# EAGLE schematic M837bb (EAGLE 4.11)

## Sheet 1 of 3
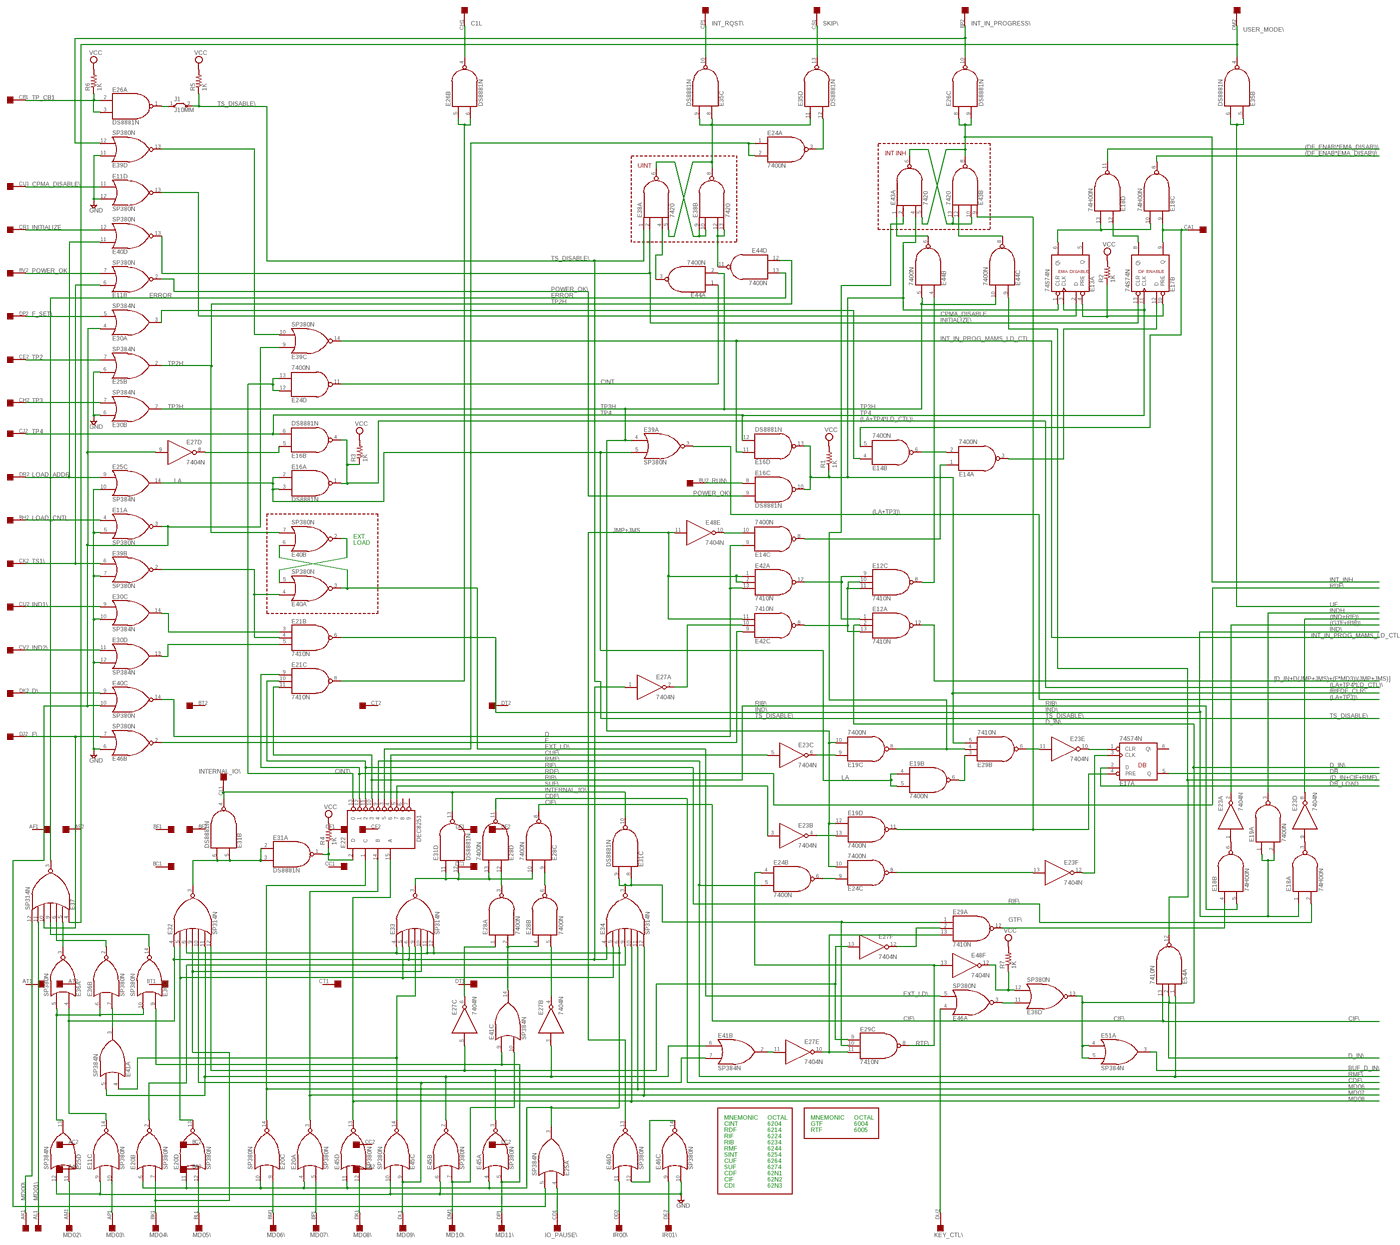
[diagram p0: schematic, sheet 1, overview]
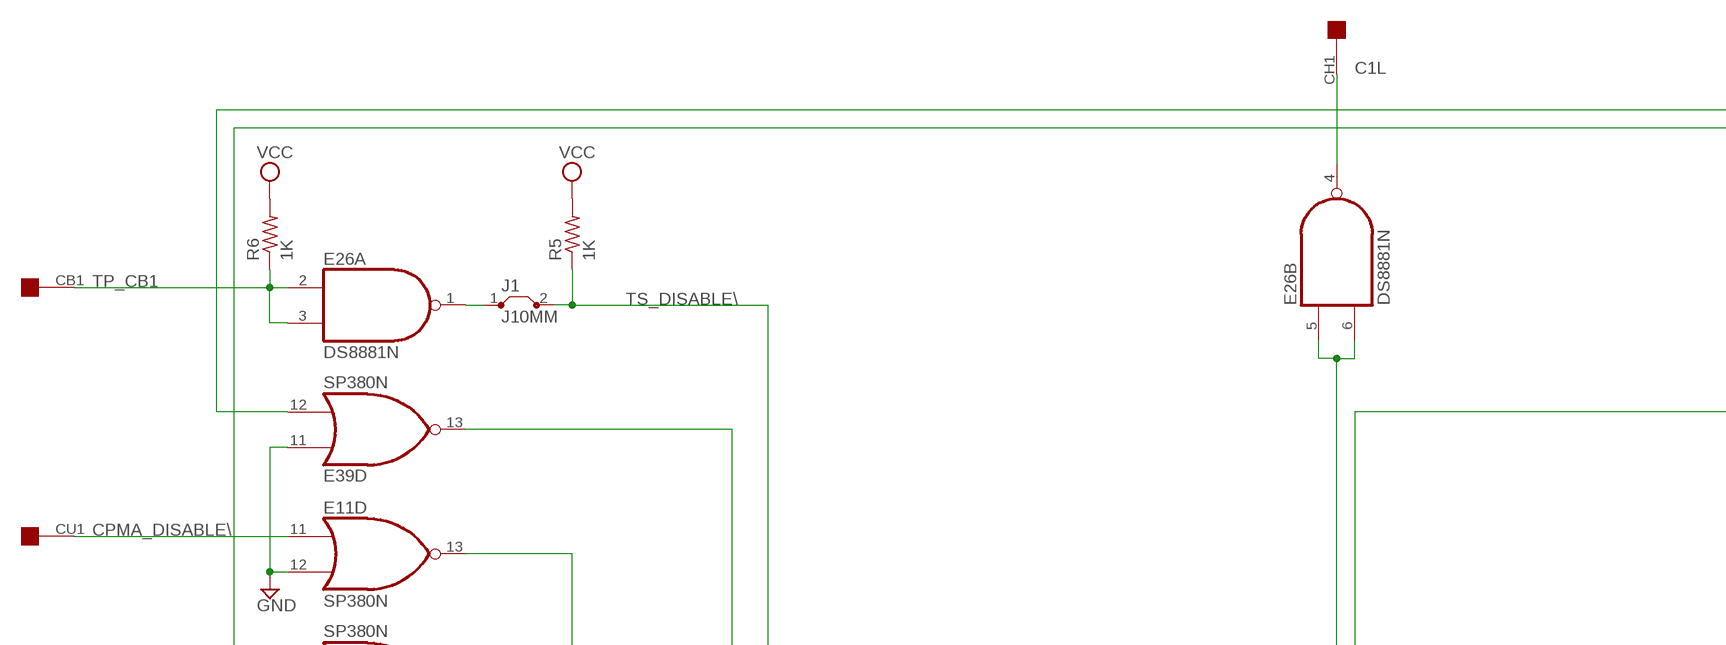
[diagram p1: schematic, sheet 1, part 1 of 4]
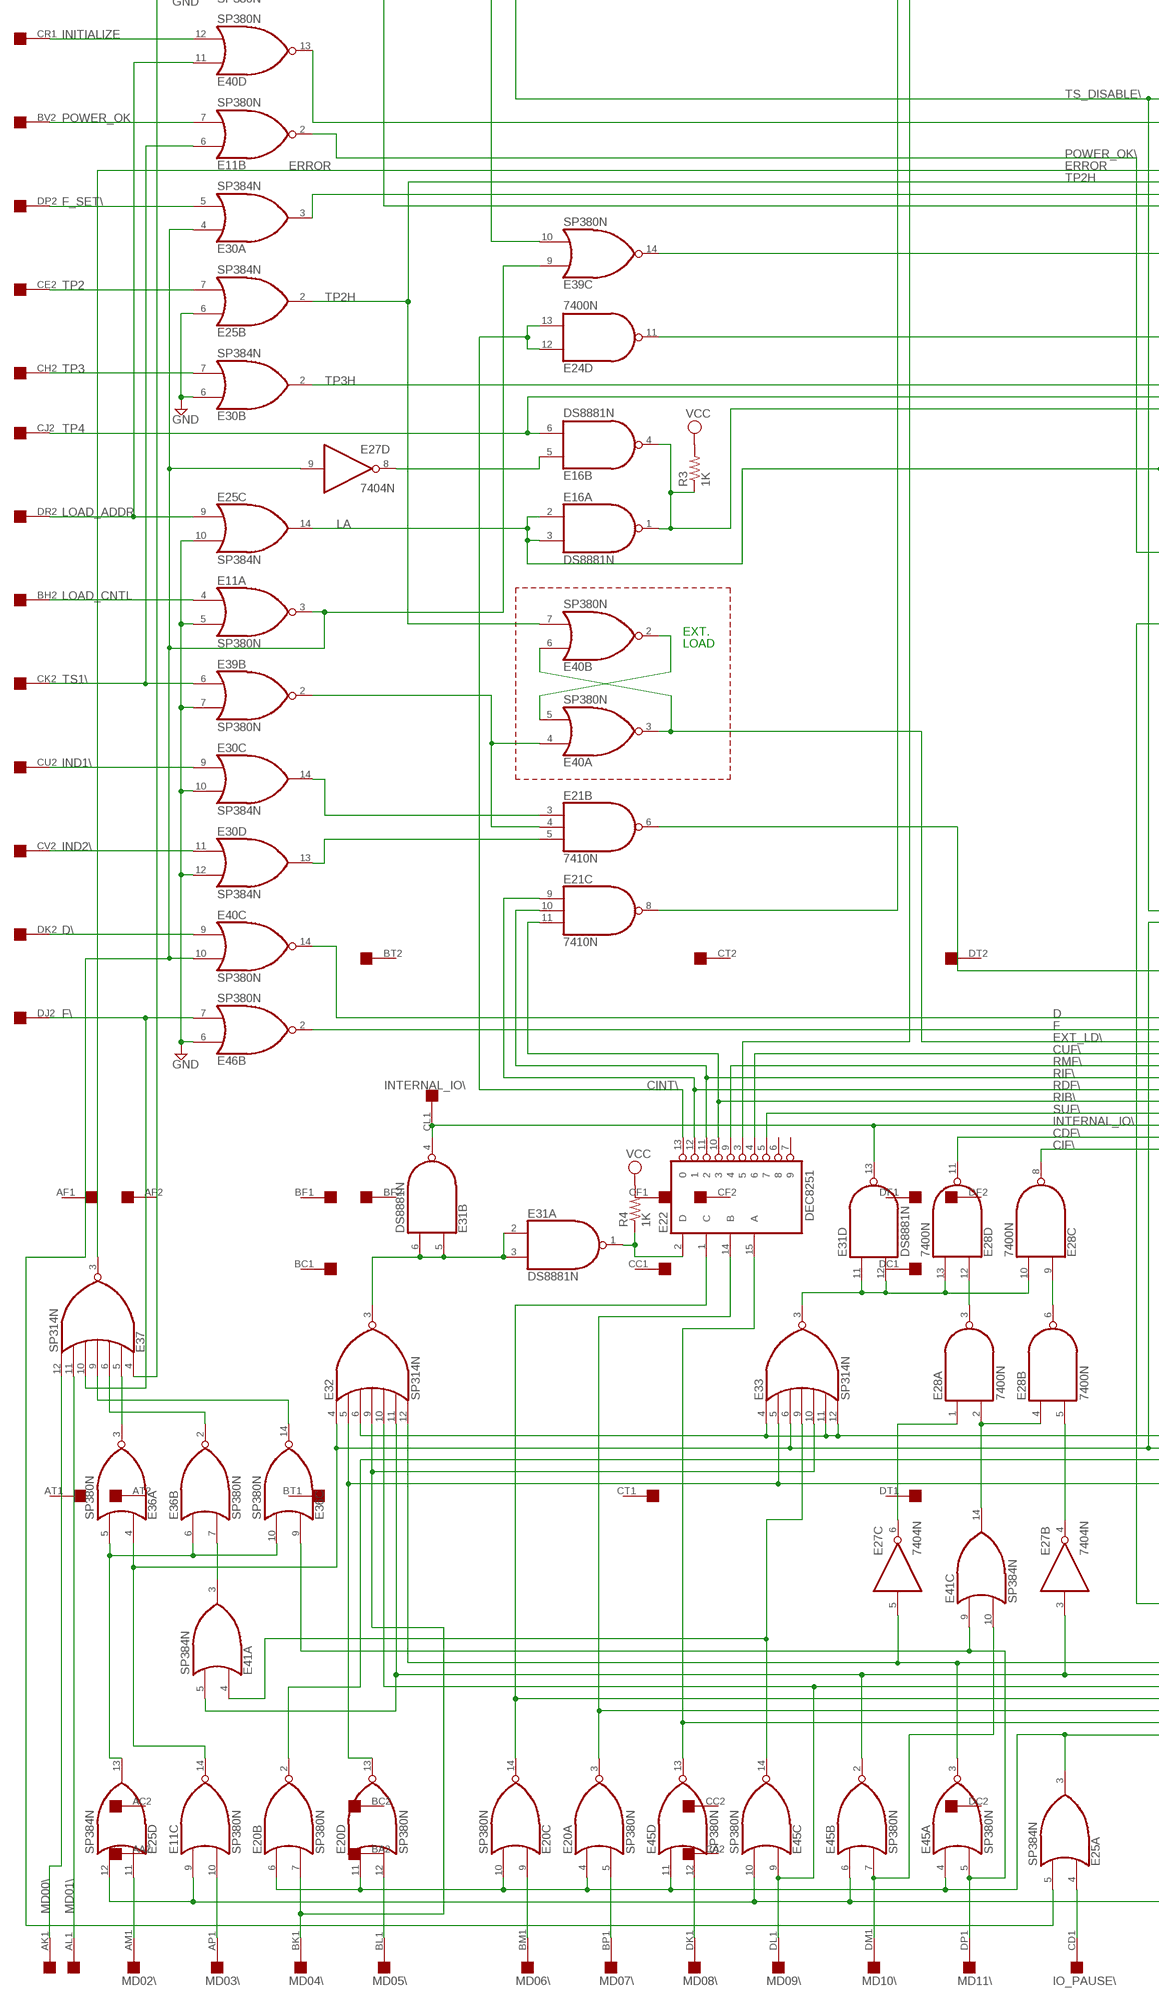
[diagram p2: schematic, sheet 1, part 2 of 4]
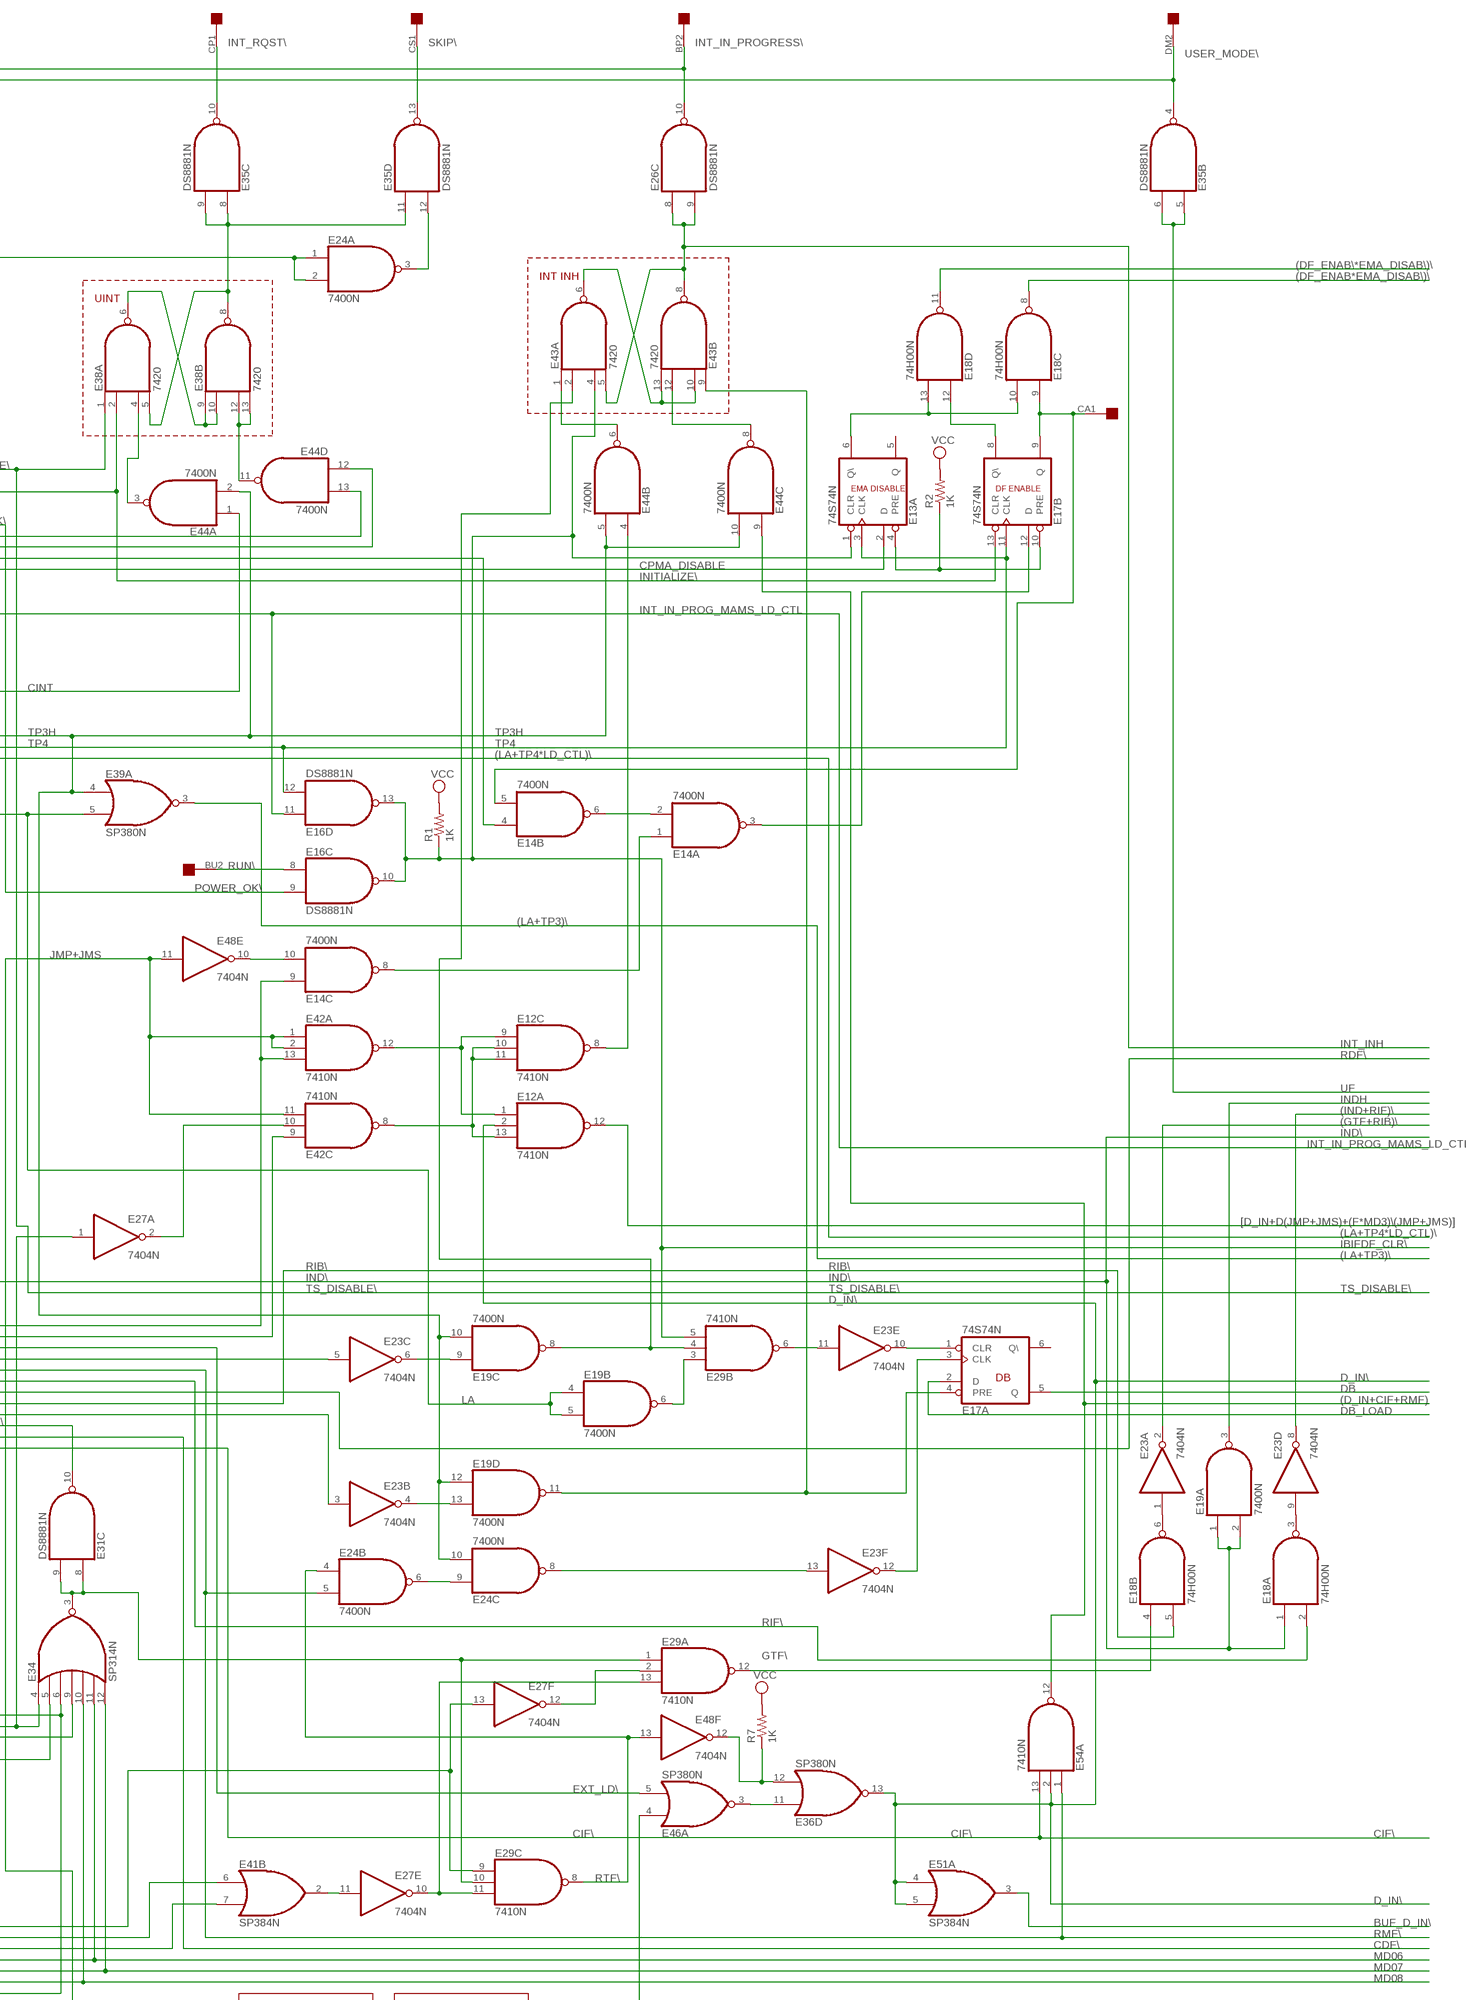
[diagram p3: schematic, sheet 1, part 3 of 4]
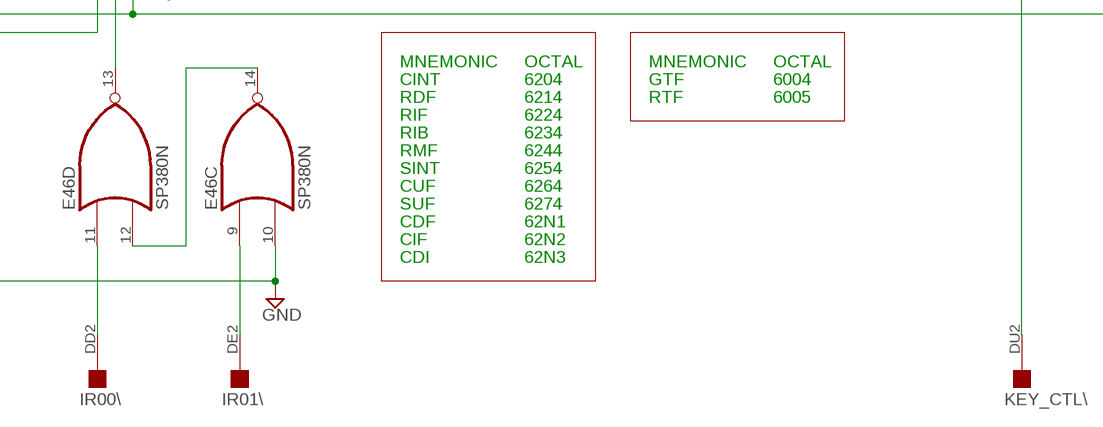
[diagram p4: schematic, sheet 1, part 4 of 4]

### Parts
E11  SP380N  [DIL14]
E12  7410N  [DIL14]
E13  74S74N  [DIL14]
E14  7400N  [DIL14]
E16  DS8881N  [DIL14]
E17  74S74N  [DIL14]
E18  74H00N  74S00N  [DIL14]
E19  7400N  [DIL14]
E20  SP380N  [DIL14]
E21  7410N  [DIL14]
E22  DEC8251  [DIL16]
E23  7404N  [DIL14]
E24  7400N  [DIL14]
E25  SP384N  [DIL14]
E26  DS8881N  [DIL14]
E27  7404N  [DIL14]
E28  7400N  [DIL14]
E29  7410N  74S10N  [DIL14]
E30  SP384N  [DIL14]
E31  DS8881N  [DIL14]
E32  SP314N  [DIL14]
E33  SP314N  [DIL14]
E34  SP314N  [DIL14]
E35  DS8881N  [DIL14]
E36  SP380N  [DIL14]
E37  SP314N  [DIL14]
E38  7420  74S20N  [DIL14]
E39  SP380N  [DIL14]
E40  SP380N  [DIL14]
E41  SP384N  [DIL14]
E42  7410N  [DIL14]
E43  7420  74S20N  [DIL14]
E44  7400N  [DIL14]
E45  SP380N  [DIL14]
E46  SP380N  [DIL14]
E48  7404N  [DIL14]
E51  SP384N  [DIL14]
E54  7410N  [DIL14]
EDGE  QUAD  [EDGE-CON8]
J1  J10MM  [10]
R1  1K  R-US_0207/10  [0207/10]
R2  1K  R-US_0207/10  [0207/10]
R3  1K  R-US_0207/10  [0207/10]
R4  1K  R-US_0207/10  [0207/10]
R5  1K  R-US_0207/10  [0207/10]
R6  1K  R-US_0207/10  [0207/10]
R7  1K  R-US_0207/10  [0207/10]

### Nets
(D_IN+CIF+RMF): E44.9(C:I0) E54.12(A:O) ; also sheet 2
(DF_ENAB*EMA_DISAB\)\: E18.8(C:O) ; also sheet 2
(DF_ENAB\*EMA_DISAB\)\: E18.11(D:O) ; also sheet 2
(GTF+RIB)\: E23.2(A:O) ; also sheet 2
(IND+RIF)\: E23.8(D:O) ; also sheet 2
(LA+TP3)\: E39.3(A:O) ; also sheet 2
(LA+TP4*LD_CTL)\: E16.1(A:O) E16.4(B:O) R3.1 ; also sheet 2
[D_IN+D(JMP+JMS)+(F*MD3)\(JMP+JMS)]: E12.12(A:O) ; also sheet 2
BUF_D_IN\: E51.3(A:O) ; also sheet 2
C1L: E26.4(B:O) EDGE.CH1
CDF\: E28.11(D:O) ; also sheet 2
CIF\: E28.8(C:O) E54.13(A:I2) ; also sheet 2
CINT: E24.11(D:O) E44.1(A:I0)
CINT\: E22.13 E24.12(D:I0) E24.13(D:I1)
CPMA_DISABLE: E11.13(D:O) E13.2(A:D)
CPMA_DISABLE\: E11.11(D:I0) EDGE.CU1
CUF\: E22.4 E23.5(C:I)
D: E14.9(C:I0) E40.14(C:O) E42.13(A:I2)
D\: E40.9(C:I0) EDGE.DK2
D_IN\: E12.2(A:I1) E36.13(D:O) E51.4(A:I0) E51.5(A:I1) E54.2(A:I1) ; also sheet 2
DB: E17.5(A:Q) ; also sheet 2
DB_LOAD: E17.2(A:D) ; also sheet 2
ERROR: E37.3(O) E44.13(D:I1)
EXT_LD\: E40.3(A:O) E40.6(B:I0) E46.5(A:I1)
F: E42.9(C:I0) E46.2(B:O)
F\: E37.10(I4) E46.7(B:I1) EDGE.DJ2
F_SET\: E30.5(A:I1) EDGE.DP2
GND [Supply]: E11.5(A:I1) E11.9(C:I0) E11.12(D:I1) E25.6(B:I0) E25.10(C:I1) E25.12(D:I1) E30.6(B:I0) E30.10(C:I1) E30.12(D:I1) E39.7(B:I1) E39.11(D:I0) E45.6(B:I0) E45.10(C:I1) E46.6(B:I0) E46.10(C:I1) ; also sheet 2,3
GTF\: E18.4(B:I0) E29.12(A:O)
IBIFDF_CLR\: E13.1(A:CLR) E16.10(C:O) E16.13(D:O) E29.5(B:I2) E43.4(A:I2) R1.1 ; also sheet 2
IND1\: E30.9(C:I0) EDGE.CU2
IND2\: E30.11(D:I0) EDGE.CV2
IND\: E18.1(A:I0) E19.1(A:I0) E19.2(A:I1) E21.6(B:O) ; also sheet 2
INDH: E19.3(A:O) ; also sheet 2
INITIALIZE: E40.12(D:I1) EDGE.CR1
INITIALIZE\: E17.13(B:CLR) E38.2(A:I1) E40.13(D:O)
INT_IN_PROG_MAMS_LD_CTL: E16.11(D:I0) E39.14(C:O) ; also sheet 2
INT_IN_PROGRESS\: E26.10(C:O) E39.12(D:I1) EDGE.BP2
INT_INH: E26.8(C:I0) E26.9(C:I1) E43.5(A:I3) E43.8(B:O) ; also sheet 2
INT_RQST\: E35.10(C:O) EDGE.CP1
INTERNAL_IO\: E31.4(B:O) E31.10(C:O) E31.13(D:O) EDGE.CL1
IO_PAUSE\: E25.4(A:I0) EDGE.CD1
IR00\: E46.11(D:I0) EDGE.DD2
IR01\: E46.9(C:I0) EDGE.DE2
JMP+JMS: E42.1(A:I0) E42.2(A:I1) E42.11(C:I2) E46.13(D:O) E48.11(E:I)
KEY_CTL\: E46.4(A:I0) EDGE.DU2
LA: E16.2(A:I0) E16.3(A:I1) E19.4(B:I0) E19.5(B:I1) E25.14(C:O) E39.5(A:I1)
LOAD_ADDR: E25.9(C:I0) E40.11(D:I0) EDGE.DR2
LOAD_CNTL: E11.4(A:I0) EDGE.BH2
MD00\: E37.12(I6) EDGE.AK1
MD01\: E37.11(I5) EDGE.AL1
MD02\: E25.11(D:I0) EDGE.AM1
MD03: E11.14(C:O) E27.1(A:I) E32.4(I0) E33.6(I2) E34.4(I0) E36.4(A:I0)
MD03\: E11.10(C:I1) EDGE.AP1
MD04\: E20.7(B:I1) E32.9(I3) E33.10(I4) EDGE.BK1
MD05\: E20.12(D:I1) EDGE.BL1
MD06: E20.14(C:O) E22.1(C) E34.11(I5) ; also sheet 2
MD06\: E20.9(C:I0) EDGE.BM1
MD07: E20.3(A:O) E22.14(B) E34.12(I6) ; also sheet 2
MD07\: E20.5(A:I1) EDGE.BP1
MD08: E22.15(A) E34.10(I4) E45.13(D:O) ; also sheet 2
MD08\: E45.12(D:I1) EDGE.DK1
MD09\: E32.10(I4) E41.7(B:I1) E45.9(C:I0) EDGE.DL1
MD10\: E41.10(C:I1) E45.7(B:I1) EDGE.DM1
MD11\: E36.9(C:I0) E41.9(C:I0) E45.5(A:I1) EDGE.DP1
N$1: E24.3(A:O) E35.12(D:I1)
N$2 [Supply]: E26.1(A:O) J1.1
N$3: E27.10(E:O) E29.11(C:I2) E29.13(A:I2)
N$4 [Supply]: E22.2(D) E31.1(A:O) R4.1
N$5 [Supply]: E31.2(A:I0) E31.3(A:I1) E31.5(B:I0) E31.6(B:I1) E32.3(O)
N$6: E36.3(A:O) E37.5(I1)
N$7: E11.3(A:O) E25.5(A:I1) E27.9(D:I) E30.4(A:I0) E39.9(C:I0) E40.10(C:I1)
N$8: E36.2(B:O) E37.6(I2)
N$9: E36.14(C:O) E37.9(I3)
N$11: E14.2(A:I1) E14.6(B:O)
N$12: E46.12(D:I1) E46.14(C:O)
N$13: E38.4(A:I2) E44.3(A:O)
N$14: E40.2(B:O) E40.5(A:I1)
N$15: E21.4(B:I1) E39.2(B:O) E40.4(A:I0)
N$16: E21.5(B:I2) E30.13(D:O)
N$17: E21.3(B:I0) E30.14(C:O)
N$18: E35.8(C:I0) E35.9(C:I1) E35.11(D:I0) E38.5(A:I3) E38.8(B:O)
N$19: E27.11(E:I) E41.2(B:O)
N$21: E38.12(B:I2) E38.13(B:I3) E44.11(D:O)
N$22: E20.4(A:I0) E20.6(B:I0) E20.10(C:I1) E20.11(D:I0) E25.3(A:O) E32.6(I2) E33.4(I0) E33.11(I5) E33.12(I6) E34.6(I2) E45.4(A:I0) E45.11(D:I0)
N$23: E38.6(A:O) E38.9(B:I0) E38.10(B:I1)
N$24: E23.13(F:I) E24.8(C:O)
N$25: E43.6(A:O) E43.10(B:I1) E43.13(B:I3)
N$26: E25.13(D:O) E36.5(A:I1) E36.6(B:I0) E36.10(C:I1)
N$27: E29.1(A:I0) E29.10(C:I1) E31.8(C:I0) E31.9(C:I1) E34.3(O)
N$28: E14.1(A:I0) E14.8(C:O)
N$29: E36.7(B:I1) E41.3(A:O)
N$30: E33.9(I3) E41.4(A:I0) E45.14(C:O)
N$31: E27.3(B:I) E32.11(I5) E41.5(A:I1) E41.6(B:I0) E45.2(B:O)
N$32: E17.3(A:CLK) E23.12(F:O)
N$33: E20.2(B:O) E34.9(I3)
N$34: E20.13(D:O) E32.5(I1) E33.5(I1) E34.5(I1)
N$35: E36.12(D:I1) E48.12(F:O) R7.1
N$36: E14.10(C:I1) E48.10(E:O)
N$37: E18.3(A:O) E23.9(D:I)
N$38: E21.8(C:O) E26.5(B:I0) E26.6(B:I1)
N$39: E16.5(B:I0) E27.8(D:O)
N$40: E12.10(C:I1) E12.11(C:I2) E12.13(A:I2) E42.8(C:O)
N$41: E39.10(C:I1) E39.13(D:O)
N$42: E13.4(A:PRE) E17.10(B:PRE) R2.1
N$43: E14.4(B:I0) E30.3(A:O)
N$44: E12.1(A:I0) E12.9(C:I0) E42.12(A:O)
N$47: E18.6(B:O) E23.1(A:I)
N$48: E27.2(A:O) E42.10(C:I1)
N$49: E14.3(A:O) E17.12(B:D)
N$50: E28.2(A:I1) E28.4(B:I0) E41.14(C:O)
N$51: E13.6(A:Q\) E18.10(C:I1) E18.13(D:I1)
N$52: E19.6(B:O) E29.3(B:I0)
N$53: E19.8(C:O) E29.4(B:I1) E43.2(A:I1)
N$54: E28.10(C:I1) E28.13(D:I1) E31.11(D:I0) E31.12(D:I1) E33.3(O)
N$55: E28.3(A:O) E28.12(D:I0)
N$56: E28.6(B:O) E28.9(C:I0)
N$57: E27.5(C:I) E27.13(F:I) E29.9(C:I0) E32.12(I6) E45.3(A:O)
N$58: E27.6(C:O) E28.1(A:I0)
N$59: E27.4(B:O) E28.5(B:I1)
N$61: E17.8(B:Q\) E18.12(D:I0)
N$62: E24.6(B:O) E24.9(C:I0)
N$63: E19.13(D:I1) E23.4(B:O)
N$64: E19.9(C:I0) E23.6(C:O)
N$65: E17.1(A:CLR) E23.10(E:O)
N$66: E23.11(E:I) E29.6(B:O)
N$67: E27.12(F:O) E29.2(A:I1)
N$68: E36.11(D:I0) E46.3(A:O)
N$69: E17.4(A:PRE) E19.11(D:O) E43.9(B:I0)
N$70: E14.5(B:I1) E17.9(B:Q) E18.9(C:I0) EDGE.CA1
N$71: E12.8(C:O) E44.4(B:I0)
N$72: E43.1(A:I0) E44.6(B:O)
N$73: E43.12(B:I2) E44.8(C:O)
POWER_OK: E11.7(B:I1) EDGE.BV2
POWER_OK\: E11.2(B:O) E16.9(C:I1)
RDF\: E21.9(C:I0) E22.12 ; also sheet 2
RIB\: E18.5(B:I1) E21.11(C:I2) E22.10
RIF\: E18.2(A:I1) E21.10(C:I1) E22.11
RMF\: E22.9 E24.5(B:I1) E54.1(A:I0) ; also sheet 2
RTF\: E24.4(B:I0) E29.8(C:O) E48.13(F:I)
RUN\: E16.8(C:I0) EDGE.BU2
SINT\: E22.3 E24.1(A:I0) E24.2(A:I1)
SKIP\: E35.13(D:O) EDGE.CS1
SUF\: E22.5 E23.3(B:I)
TP2: E25.7(B:I1) EDGE.CE2
TP2H: E25.2(B:O) E40.7(B:I1) E44.12(D:I0)
TP3: E30.7(B:I1) EDGE.CH2
TP3H: E19.10(C:I1) E19.12(D:I0) E24.10(C:I1) E30.2(B:O) E39.4(A:I0) E44.2(A:I1) E44.5(B:I1) E44.10(C:I1)
TP4: E13.3(A:CLK) E16.6(B:I1) E16.12(D:I1) E17.11(B:CLK) EDGE.CJ2
TP_CB1: E26.2(A:I0) E26.3(A:I1) EDGE.CB1 R6.1
TS1\: E11.6(B:I0) E39.6(B:I0) EDGE.CK2
TS_DISABLE\ [Supply]: E38.1(A:I0) J1.2 R5.1 ; also sheet 2
UF: E35.5(B:I0) E35.6(B:I1) ; also sheet 2
USER_MODE\: E35.4(B:O) E37.4(I0) EDGE.DM2
VCC [Supply]: R1.2 R2.2 R3.2 R4.2 R5.2 R6.2 R7.2 ; also sheet 2,3
Unconnected: E13.5(A:Q) E13.8(B:Q\) E13.9(B:Q) E13.10(B:PRE) E13.11(B:CLK) E13.12(B:D) E13.13(B:CLR) E17.6(A:Q\) E21.1(A:I0) E21.2(A:I1) E21.12(A:O) E21.13(A:I2) E22.6 E22.7 E26.11(D:I0) E26.12(D:I1) E26.13(D:O) E35.1(A:O) E35.2(A:I0) E35.3(A:I1) E41.11(D:I0) E41.12(D:I1) E41.13(D:O) E42.3(B:I0) E42.4(B:I1) E42.5(B:I2) E42.6(B:O) E48.1(A:I) E48.2(A:O) E48.3(B:I) E48.4(B:O) E54.8(C:O) E54.9(C:I0) E54.10(C:I1) E54.11(C:I2) EDGE.AB2 EDGE.AC1 EDGE.AD1 EDGE.AE1 EDGE.AH1 EDGE.AJ1 EDGE.AJ2 EDGE.AK2 EDGE.AL2 EDGE.AM2 EDGE.AN1 EDGE.AN2 EDGE.AP2 EDGE.AR1 EDGE.AR2 EDGE.AS1 EDGE.AS2 EDGE.AU1 EDGE.AU2 EDGE.AV2 EDGE.BB2 EDGE.BD1 EDGE.BD2 EDGE.BE1 EDGE.BE2 EDGE.BH1 EDGE.BJ1 EDGE.BJ2 EDGE.BK2 EDGE.BL2 EDGE.BM2 EDGE.BN1 EDGE.BN2 EDGE.BR1 EDGE.BR2 EDGE.BS2 EDGE.CB2 EDGE.CD2 EDGE.CE1 EDGE.CJ1 EDGE.CK1 EDGE.CL2 EDGE.CM1 EDGE.CM2 EDGE.CN1 EDGE.CN2 EDGE.CP2 EDGE.CR2 EDGE.CS2 EDGE.CV1 EDGE.DA1 EDGE.DA2 EDGE.DB1 EDGE.DB2 EDGE.DD1 EDGE.DE1 EDGE.DH1 EDGE.DH2 EDGE.DJ1 EDGE.DL2 EDGE.DN1 EDGE.DN2 EDGE.DS2 EDGE.DV2

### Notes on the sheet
- INT INH
- UINT
- EMA DISABLE | DF ENABLE
- EXT.
- LOAD
- DB
- MNEMONIC | OCTAL | MNEMONIC | OCTAL
- CINT | 6204 | GTF | 6004
- RDF | 6214 | RTF | 6005
- RIF | 6224
- RIB | 6234
- RMF | 6244
- SINT | 6254
- CUF | 6264
- SUF | 6274
- CDF | 62N1
- CIF | 62N2
- CDI | 62N3

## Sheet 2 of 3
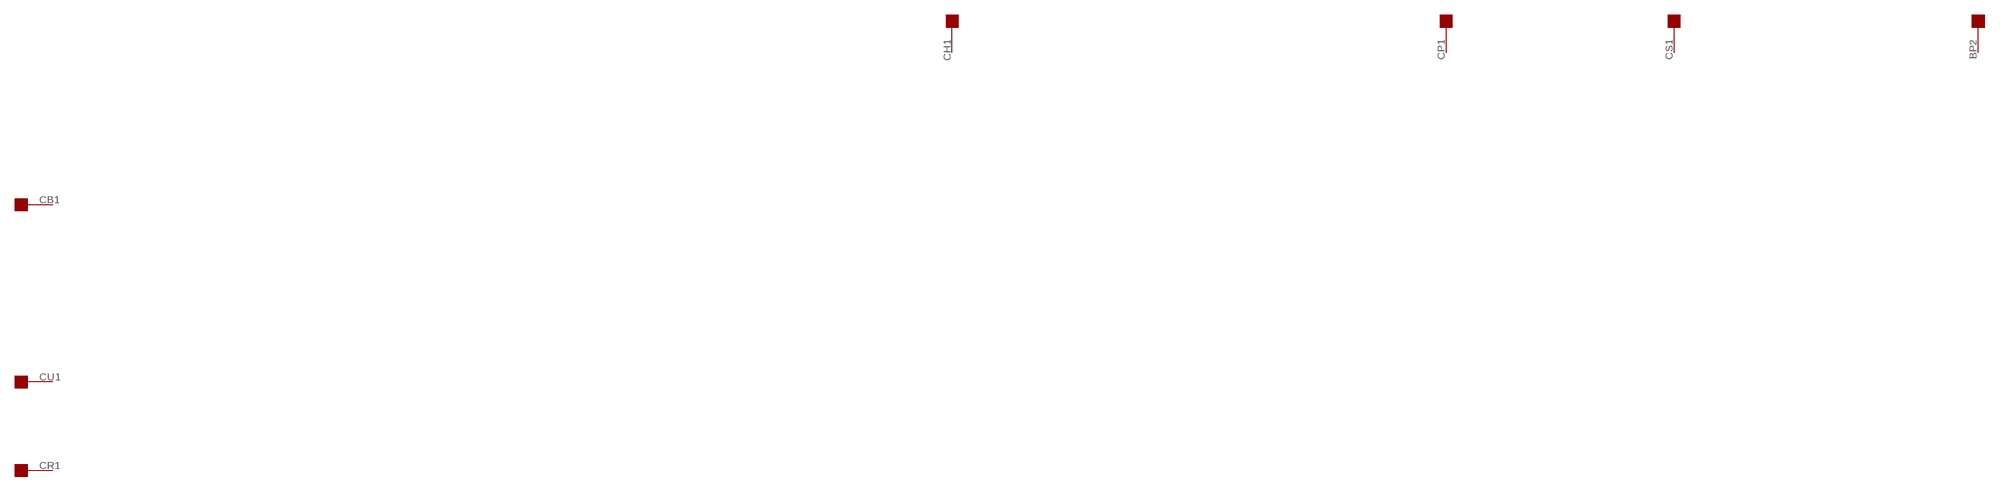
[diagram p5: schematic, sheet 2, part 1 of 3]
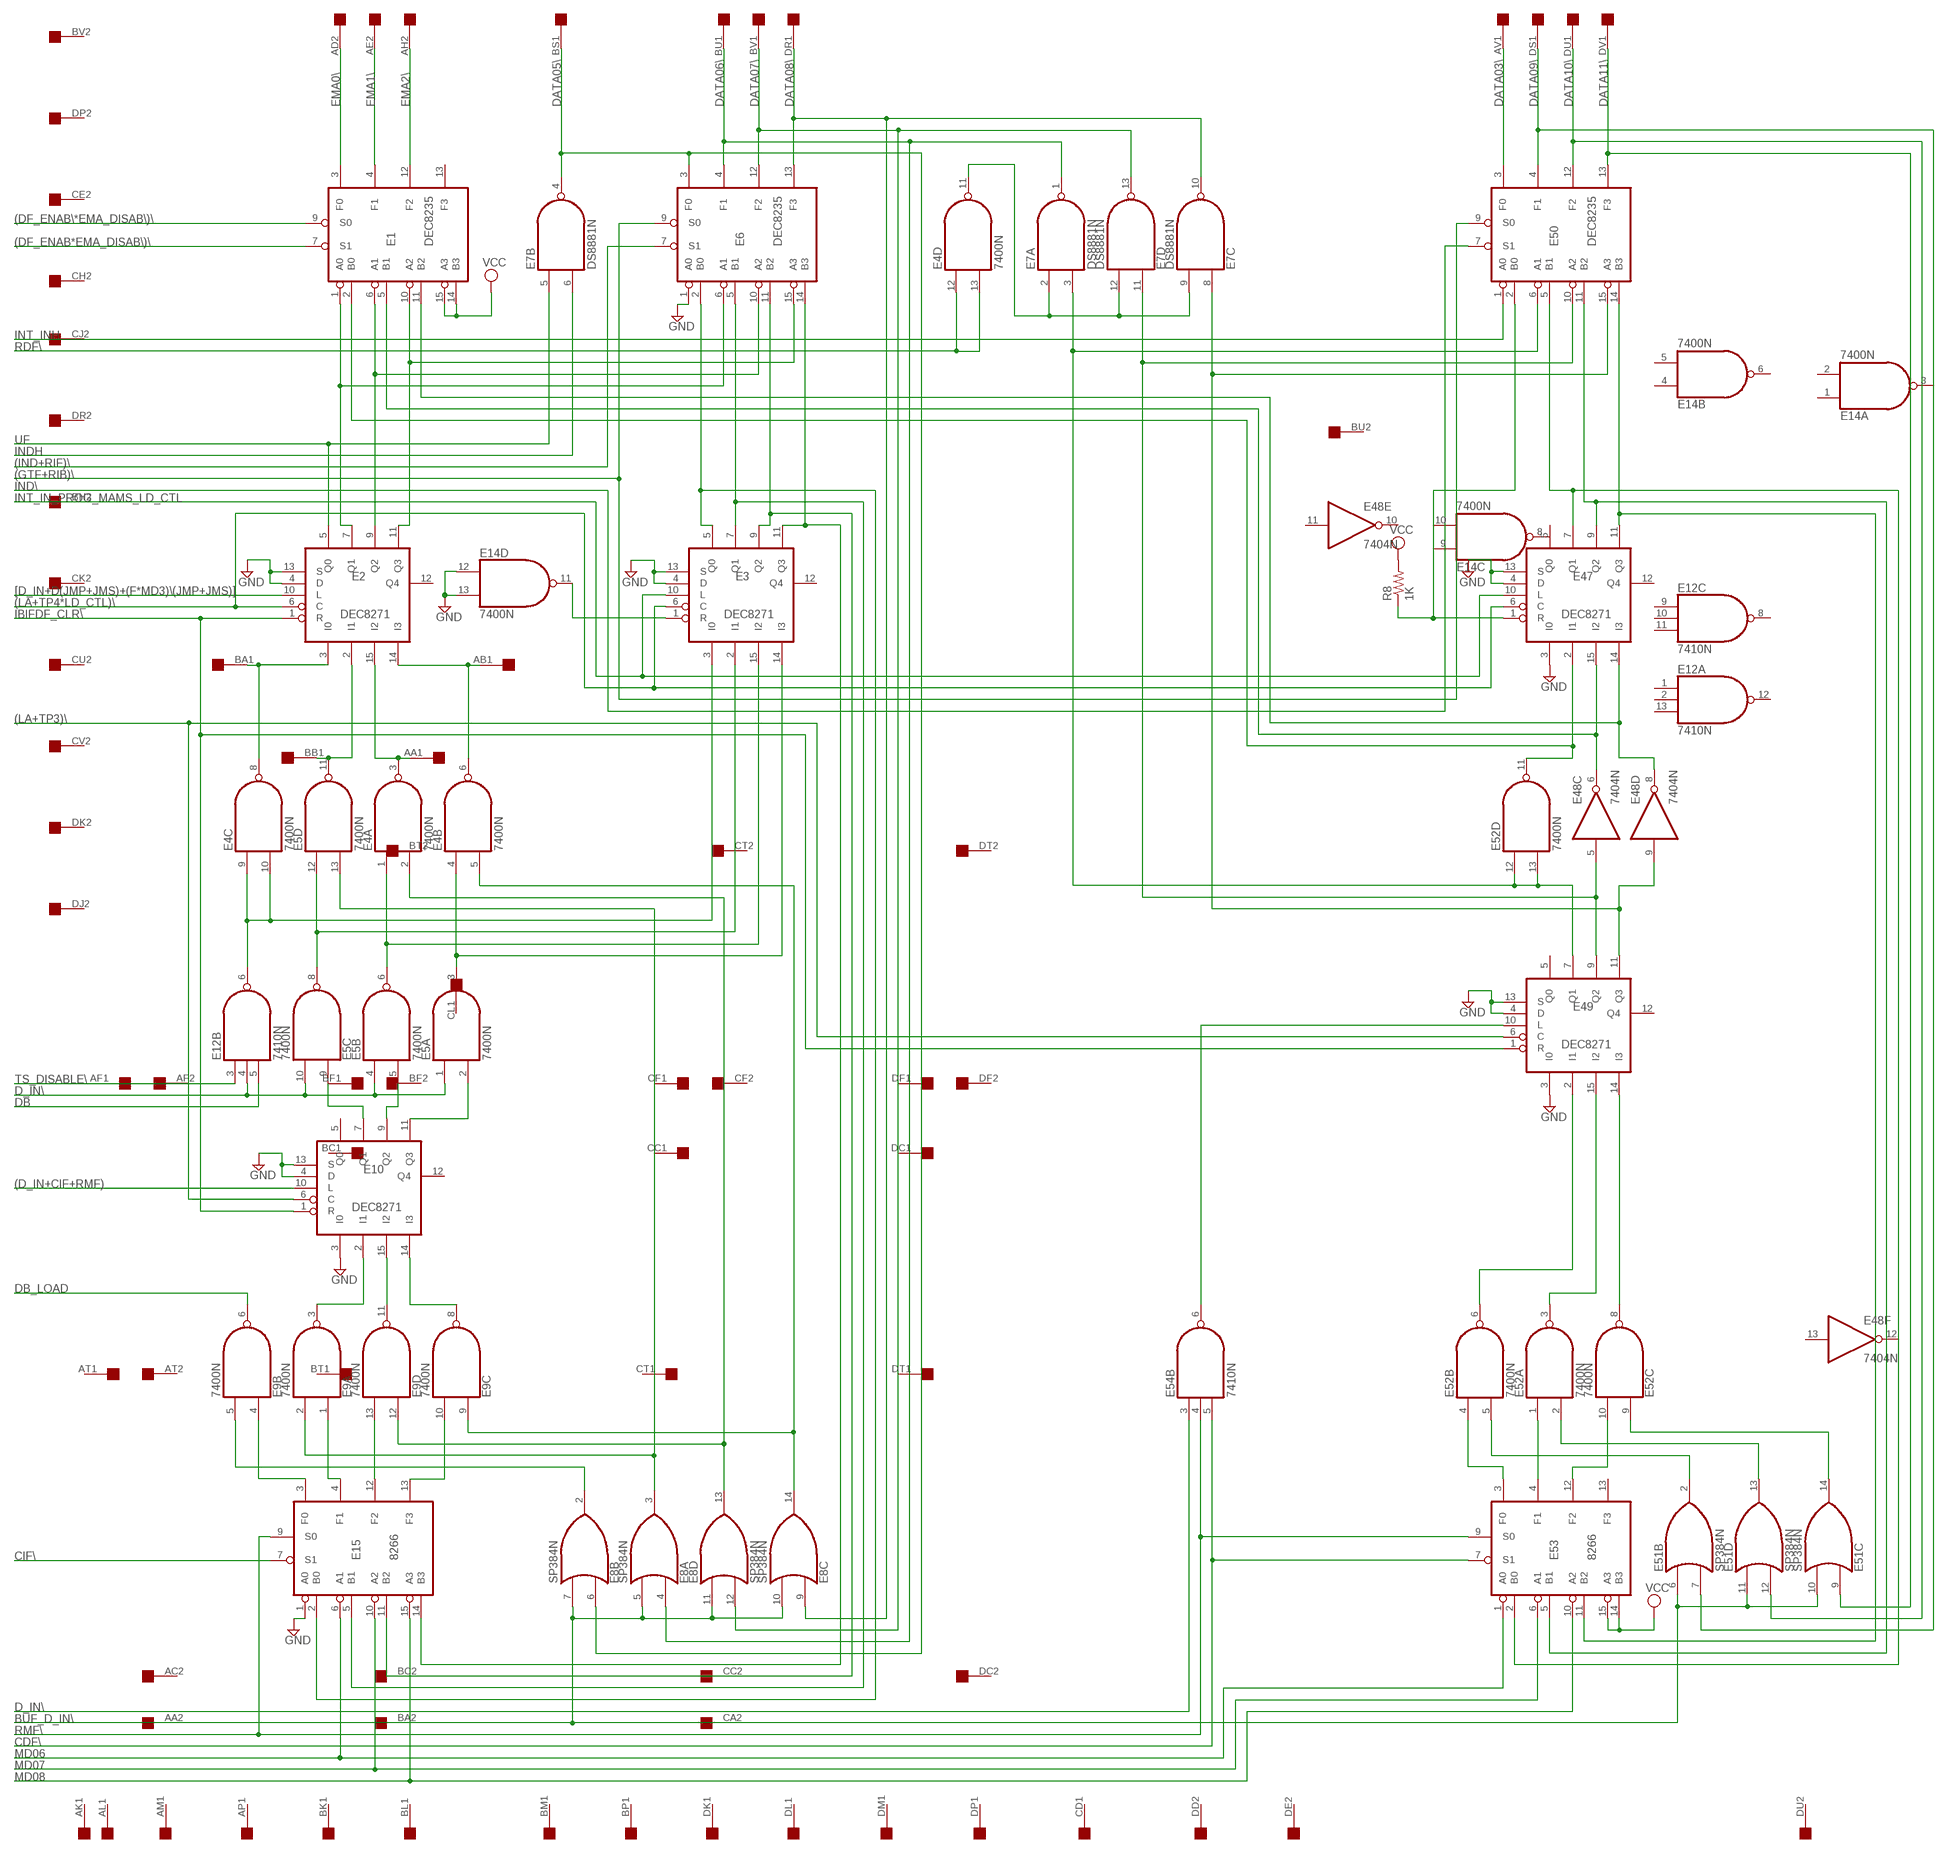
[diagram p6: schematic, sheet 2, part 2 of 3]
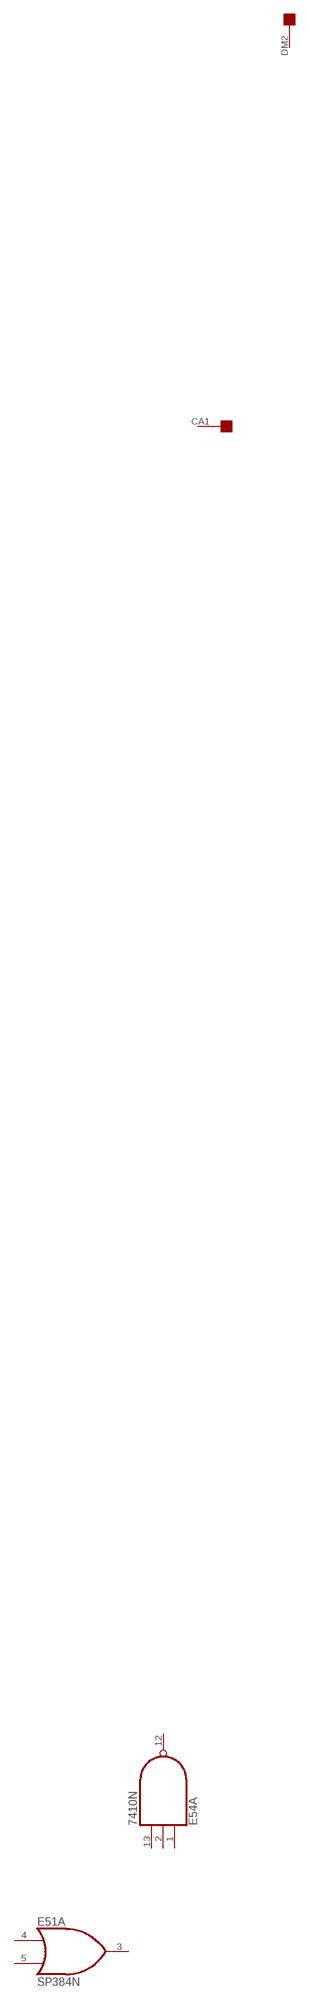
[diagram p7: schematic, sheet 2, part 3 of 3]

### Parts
E1  DEC8235  [DIL16]
E2  DEC8271  [DIL16]
E3  DEC8271  [DIL16]
E4  7400N  [DIL14]
E5  7400N  [DIL14]
E6  DEC8235  [DIL16]
E7  DS8881N  [DIL14]
E8  SP384N  [DIL14]
E9  7400N  [DIL14]
E10  DEC8271  [DIL16]
E15  8266  [DIL16]
E47  DEC8271  [DIL16]
E49  DEC8271  [DIL16]
E50  DEC8235  [DIL16]
E52  7400N  [DIL14]
E53  8266  [DIL16]
R8  1K  R-US_0207/10  [0207/10]

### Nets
(D_IN+CIF+RMF): E10.10(L) ; also sheet 1
(DF_ENAB*EMA_DISAB\)\: E1.7(S1) ; also sheet 1
(DF_ENAB\*EMA_DISAB\)\: E1.9(S0) ; also sheet 1
(GTF+RIB)\: E6.9(S0) E50.9(S0) ; also sheet 1
(IND+RIF)\: E6.7(S1) ; also sheet 1
(LA+TP3)\: E10.6(C) E49.6(C) ; also sheet 1
(LA+TP4*LD_CTL)\: E2.6(C) E3.6(C) E47.6(C) ; also sheet 1
[D_IN+D(JMP+JMS)+(F*MD3)\(JMP+JMS)]: E2.10(L) ; also sheet 1
BUF_D_IN\: E8.5(A:I1) E8.7(B:I1) E8.10(C:I1) E8.11(D:I0) E51.6(B:I0) E51.10(C:I1) E51.11(D:I0) ; also sheet 1
CDF\: E53.7(S1) E54.5(B:I2) ; also sheet 1
CIF\: E15.7(S1) ; also sheet 1
D_IN\: E5.1(A:I0) E5.4(B:I0) E5.10(C:I1) E12.4(B:I1) E54.3(B:I0) ; also sheet 1
DATA03\: E50.3(F0) EDGE.AV1
DATA05\: E6.3(F0) E7.4(B:O) E8.6(B:I0) EDGE.BS1
DATA06\: E6.4(F1) E7.1(A:O) E8.4(A:I0) EDGE.BU1
DATA07\: E6.12(F2) E7.13(D:O) E8.12(D:I1) EDGE.BV1
DATA08\: E6.13(F3) E7.10(C:O) E8.9(C:I0) EDGE.DR1
DATA09\: E50.4(F1) E51.7(B:I1) EDGE.DS1
DATA10\: E50.12(F2) E51.12(D:I1) EDGE.DU1
DATA11\: E50.13(F3) E51.9(C:I0) EDGE.DV1
DB: E12.5(B:I2) ; also sheet 1
DB_LOAD: E9.6(B:O) ; also sheet 1
EMA0\: E1.3(F0) EDGE.AD2
EMA1\: E1.4(F1) EDGE.AE2
EMA2\: E1.12(F2) EDGE.AH2
GND [Supply]: E2.4(D) E2.13(S) E3.4(D) E3.13(S) E6.1(A0) E10.3(I0) E10.4(D) E10.13(S) E14.12(D:I0) E14.13(D:I1) E15.1(A0) E47.3(I0) E47.4(D) E47.13(S) E49.3(I0) E49.4(D) E49.13(S) ; also sheet 1,3
IBIFDF_CLR\: E2.1(R) E10.1(R) E49.1(R) ; also sheet 1
IND\: E50.7(S1) ; also sheet 1
INDH: E7.6(B:I1) ; also sheet 1
INT_IN_PROG_MAMS_LD_CTL: E3.10(L) E47.10(L) ; also sheet 1
INT_INH: E50.1(A0) ; also sheet 1
MD06: E15.6(A1) E53.1(A0) ; also sheet 1
MD07: E15.10(A2) E53.6(A1) ; also sheet 1
MD08: E15.15(A3) E53.10(A2) ; also sheet 1
N$10: E3.5(Q0) E6.2(B0) E15.2(B0)
N$20: E3.7(Q1) E6.5(B1) E15.5(B1)
N$45: E3.9(Q2) E6.11(B2) E15.11(B2)
N$60: E3.11(Q3) E6.14(B3) E15.14(B3)
N$74: E9.4(B:I0) E15.3(F0)
N$75: E9.1(A:I0) E15.4(F1)
N$76: E9.13(D:I1) E15.12(F2)
N$77: E9.10(C:I1) E15.13(F3)
N$78: E8.2(B:O) E9.5(B:I1)
N$79: E5.13(D:I1) E8.3(A:O) E9.2(A:I1)
N$80: E4.2(A:I1) E8.13(D:O) E9.12(D:I0)
N$81: E4.5(B:I1) E8.14(C:O) E9.9(C:I0)
N$82: E9.11(D:O) E10.15(I2)
N$83: E9.3(A:O) E10.2(I1)
N$84: E9.8(C:O) E10.14(I3)
N$86: E3.14(I3) E4.4(B:I0) E5.3(A:O)
N$87: E3.15(I2) E4.1(A:I0) E5.6(B:O)
N$88: E5.9(C:I0) E10.7(Q1)
N$89: E5.5(B:I1) E10.9(Q2)
N$90: E5.2(A:I1) E10.11(Q3)
N$93: E3.2(I1) E5.8(C:O) E5.12(D:I0)
N$94: E3.3(I0) E4.9(C:I0) E4.10(C:I1) E12.6(B:O)
N$95: E2.2(I1) E5.11(D:O) EDGE.BB1
N$96: E2.15(I2) E4.3(A:O) EDGE.AA1
N$100: E2.14(I3) E4.6(B:O) EDGE.AB1
N$101: E2.3(I0) E4.8(C:O) EDGE.BA1
N$102: E1.1(A0) E2.7(Q1) E6.6(A1)
N$103: E1.6(A1) E2.9(Q2) E6.10(A2)
N$104: E1.10(A2) E2.11(Q3) E6.15(A3)
N$105: E1.11(B2) E47.14(I3) E48.8(D:O)
N$106: E1.5(B1) E47.15(I2) E48.6(C:O)
N$107: E1.2(B0) E47.2(I1) E52.11(D:O)
N$110: E49.10(L) E54.6(B:O)
N$113: E4.11(D:O) E7.2(A:I0) E7.9(C:I1) E7.12(D:I1)
N$118: E7.11(D:I0) E48.5(C:I) E49.9(Q2) E50.10(A2)
N$119: E7.8(C:I0) E48.9(D:I) E49.11(Q3) E50.15(A3)
N$120: E51.2(B:O) E52.5(B:I1)
N$121: E7.3(A:I1) E49.7(Q1) E50.6(A1) E52.12(D:I0) E52.13(D:I1)
N$122: E51.13(D:O) E52.2(A:I1)
N$124: E51.14(C:O) E52.9(C:I0)
N$126: E52.1(A:I0) E53.4(F1)
N$128: E47.11(Q3) E50.14(B3) E53.11(B2)
N$129: E47.9(Q2) E50.11(B2) E53.5(B1)
N$130: E47.7(Q1) E50.5(B1) E53.2(B0)
N$135: E52.10(C:I1) E53.12(F2)
N$137: E3.1(R) E14.11(D:O)
N$140: E52.4(B:I0) E53.3(F0)
N$141: E49.14(I3) E52.8(C:O)
N$142: E49.15(I2) E52.3(A:O)
N$143: E49.2(I1) E52.6(B:O)
N$145: E47.1(R) E50.2(B0) R8.1
RDF\: E4.12(D:I0) E4.13(D:I1) ; also sheet 1
RMF\: E15.9(S0) E53.9(S0) E54.4(B:I1) ; also sheet 1
TS_DISABLE\ [Supply]: E12.3(B:I0) ; also sheet 1
UF: E2.5(Q0) E7.5(B:I0) ; also sheet 1
VCC [Supply]: E1.14(B3) E1.15(A3) E53.14(B3) E53.15(A3) R8.2 ; also sheet 1,3
Unconnected: E1.13(F3) E2.12(Q4) E3.12(Q4) E10.5(Q0) E10.12(Q4) E47.5(Q0) E47.12(Q4) E49.5(Q0) E49.12(Q4) E53.13(F3)

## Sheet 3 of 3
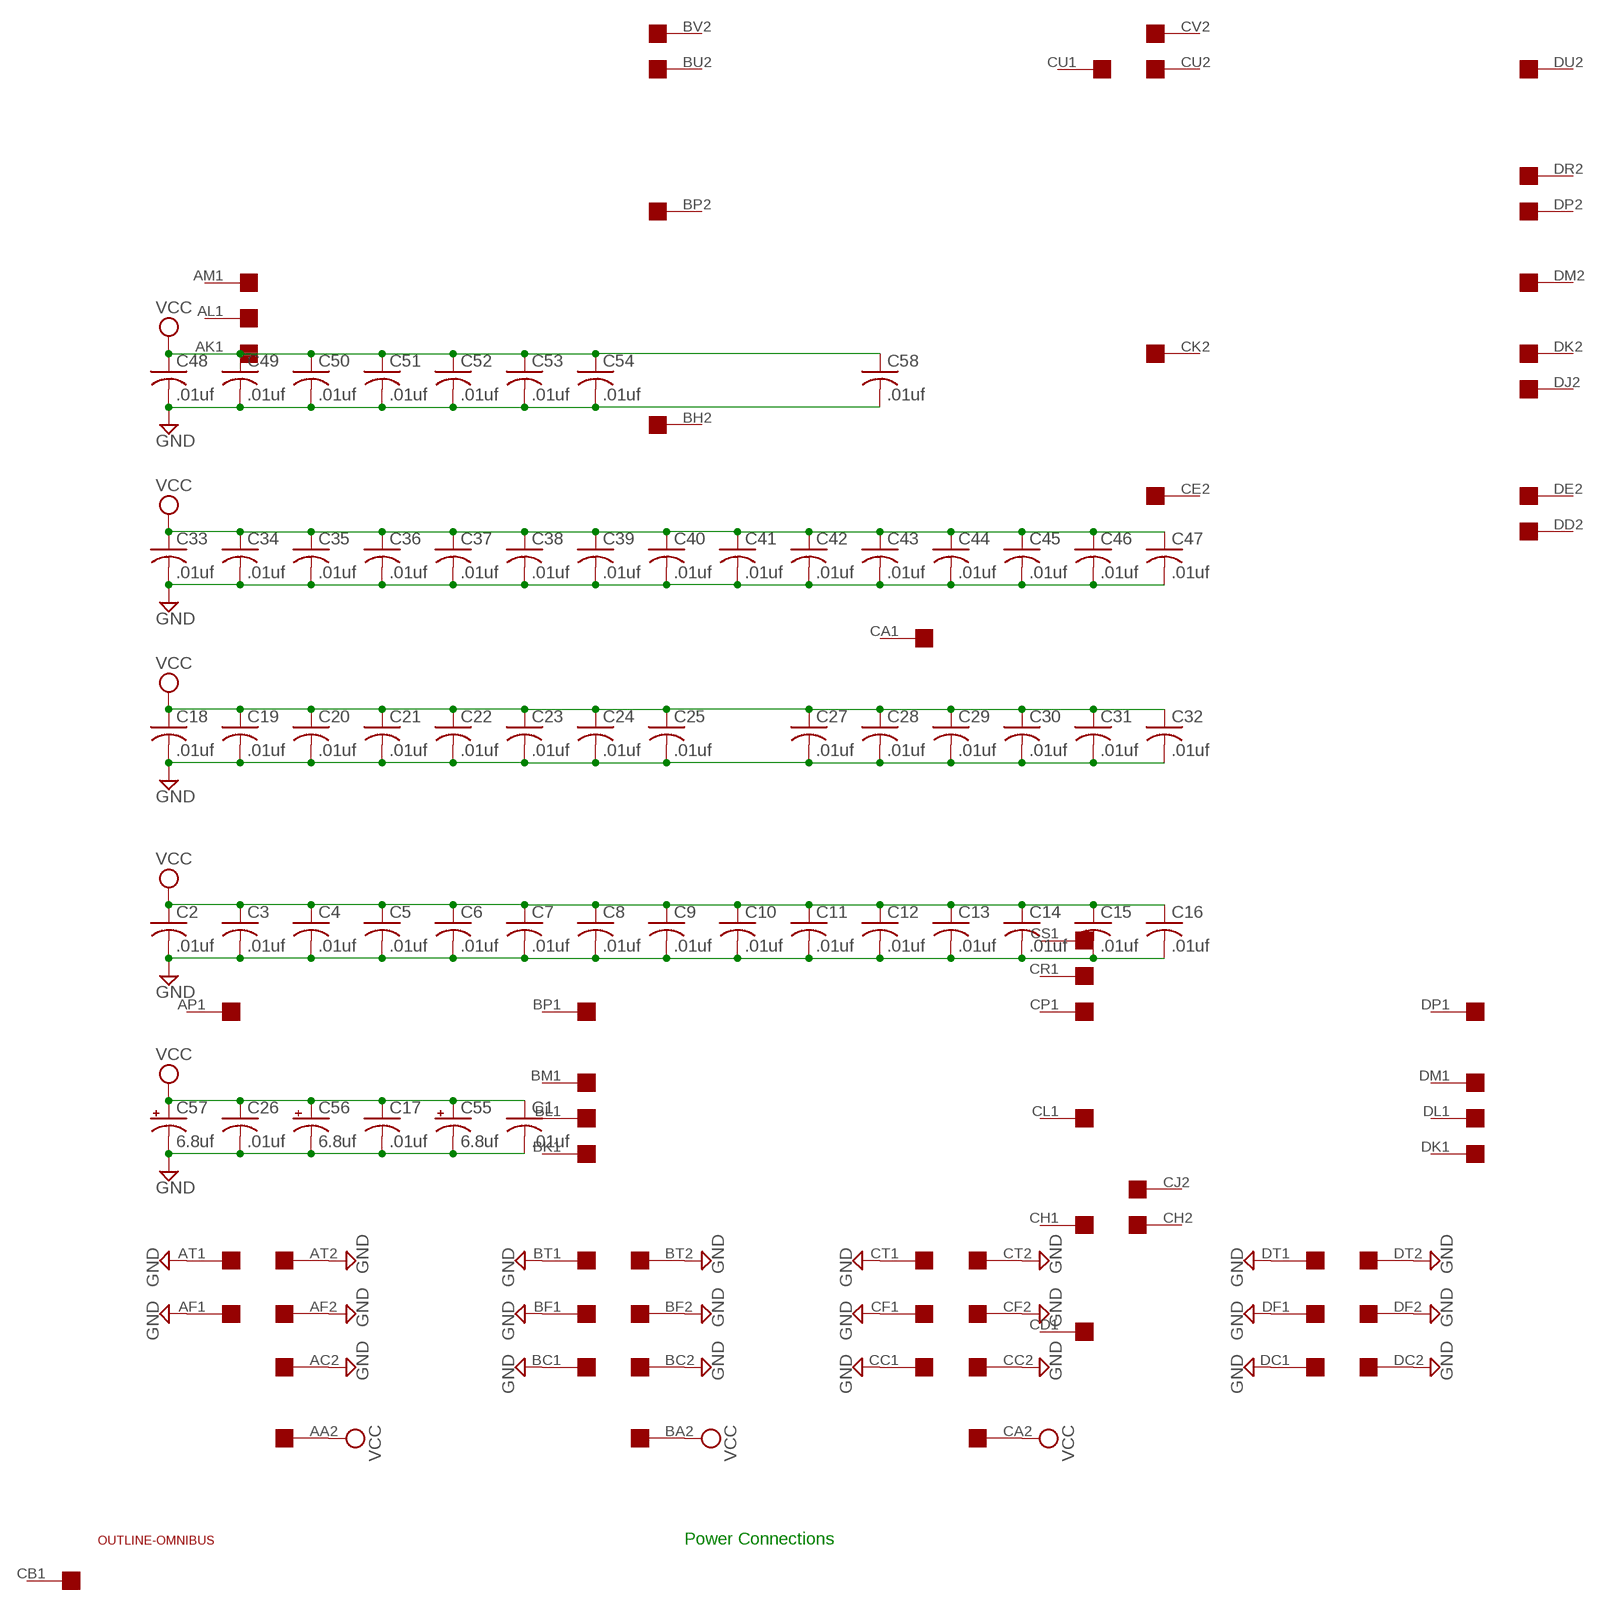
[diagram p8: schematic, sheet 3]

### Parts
C1  .01uf  C-US050-025X075  [C050-025X075]
C2  .01uf  C-US050-025X075  [C050-025X075]
C3  .01uf  C-US050-025X075  [C050-025X075]
C4  .01uf  C-US050-025X075  [C050-025X075]
C5  .01uf  C-US050-025X075  [C050-025X075]
C6  .01uf  C-US050-025X075  [C050-025X075]
C7  .01uf  C-US050-025X075  [C050-025X075]
C8  .01uf  C-US050-025X075  [C050-025X075]
C9  .01uf  C-US050-025X075  [C050-025X075]
C10  .01uf  C-US050-025X075  [C050-025X075]
C11  .01uf  C-US050-025X075  [C050-025X075]
C12  .01uf  C-US050-025X075  [C050-025X075]
C13  .01uf  C-US050-025X075  [C050-025X075]
C14  .01uf  C-US050-025X075  [C050-025X075]
C15  .01uf  C-US050-025X075  [C050-025X075]
C16  .01uf  C-US050-025X075  [C050-025X075]
C17  .01uf  C-US050-025X075  [C050-025X075]
C18  .01uf  C-US050-025X075  [C050-025X075]
C19  .01uf  C-US050-025X075  [C050-025X075]
C20  .01uf  C-US050-025X075  [C050-025X075]
C21  .01uf  C-US050-025X075  [C050-025X075]
C22  .01uf  C-US050-025X075  [C050-025X075]
C23  .01uf  C-US050-025X075  [C050-025X075]
C24  .01uf  C-US050-025X075  [C050-025X075]
C25  .01uf  C-US050-025X075  [C050-025X075]
C26  .01uf  C-US050-025X075  [C050-025X075]
C27  .01uf  C-US050-025X075  [C050-025X075]
C28  .01uf  C-US050-025X075  [C050-025X075]
C29  .01uf  C-US050-025X075  [C050-025X075]
C30  .01uf  C-US050-025X075  [C050-025X075]
C31  .01uf  C-US050-025X075  [C050-025X075]
C32  .01uf  C-US050-025X075  [C050-025X075]
C33  .01uf  C-US050-025X075  [C050-025X075]
C34  .01uf  C-US050-025X075  [C050-025X075]
C35  .01uf  C-US050-025X075  [C050-025X075]
C36  .01uf  C-US050-025X075  [C050-025X075]
C37  .01uf  C-US050-025X075  [C050-025X075]
C38  .01uf  C-US050-025X075  [C050-025X075]
C39  .01uf  C-US050-025X075  [C050-025X075]
C40  .01uf  C-US050-025X075  [C050-025X075]
C41  .01uf  C-US050-025X075  [C050-025X075]
C42  .01uf  C-US050-025X075  [C050-025X075]
C43  .01uf  C-US050-025X075  [C050-025X075]
C44  .01uf  C-US050-025X075  [C050-025X075]
C45  .01uf  C-US050-025X075  [C050-025X075]
C46  .01uf  C-US050-025X075  [C050-025X075]
C47  .01uf  C-US050-025X075  [C050-025X075]
C48  .01uf  C-US050-025X075  [C050-025X075]
C49  .01uf  C-US050-025X075  [C050-025X075]
C50  .01uf  C-US050-025X075  [C050-025X075]
C51  .01uf  C-US050-025X075  [C050-025X075]
C52  .01uf  C-US050-025X075  [C050-025X075]
C53  .01uf  C-US050-025X075  [C050-025X075]
C54  .01uf  C-US050-025X075  [C050-025X075]
C55  6.8uf  CPOL-USE22-6AXIAL  [E22-6]
C56  6.8uf  CPOL-USE22-6AXIAL  [E22-6]
C57  6.8uf  CPOL-USE22-6AXIAL  [E22-6]
C58  .01uf  C-US050-025X075  [C050-025X075]
U$1  OUTLINE-OMNIBUS  [OMNIBUS]

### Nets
GND [Supply]: C1.2 C2.2 C3.2 C4.2 C5.2 C6.2 C7.2 C8.2 C9.2 C10.2 C11.2 C12.2 C13.2 C14.2 C15.2 C16.2 C17.2 C18.2 C19.2 C20.2 C21.2 C22.2 C23.2 C24.2 C25.2 C26.2 C27.2 C28.2 C29.2 C30.2 C31.2 C32.2 C33.2 C34.2 C35.2 C36.2 C37.2 C38.2 C39.2 C40.2 C41.2 C42.2 C43.2 C44.2 C45.2 C46.2 C47.2 C48.2 C49.2 C50.2 C51.2 C52.2 C53.2 C54.2 C55.- C56.- C57.- C58.2 EDGE.AC2 EDGE.AF1 EDGE.AF2 EDGE.AT1 EDGE.AT2 EDGE.BC1 EDGE.BC2 EDGE.BF1 EDGE.BF2 EDGE.BT1 EDGE.BT2 EDGE.CC1 EDGE.CC2 EDGE.CF1 EDGE.CF2 EDGE.CT1 EDGE.CT2 EDGE.DC1 EDGE.DC2 EDGE.DF1 EDGE.DF2 EDGE.DT1 EDGE.DT2 ; also sheet 1,2
VCC [Supply]: C1.1 C2.1 C3.1 C4.1 C5.1 C6.1 C7.1 C8.1 C9.1 C10.1 C11.1 C12.1 C13.1 C14.1 C15.1 C16.1 C17.1 C18.1 C19.1 C20.1 C21.1 C22.1 C23.1 C24.1 C25.1 C26.1 C27.1 C28.1 C29.1 C30.1 C31.1 C32.1 C33.1 C34.1 C35.1 C36.1 C37.1 C38.1 C39.1 C40.1 C41.1 C42.1 C43.1 C44.1 C45.1 C46.1 C47.1 C48.1 C49.1 C50.1 C51.1 C52.1 C53.1 C54.1 C55.+ C56.+ C57.+ C58.1 EDGE.AA2 EDGE.BA2 EDGE.CA2 ; also sheet 1,2

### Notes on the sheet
- Power Connections

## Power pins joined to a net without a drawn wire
GND: E1.8(GND) E2.8(GND) E3.8(GND) E4.7(P:GND) E5.7(P:GND) E6.8(GND) E7.7(P:GND) E8.1(GND) E9.7(P:GND) E10.8(GND) E11.1(P:GND) E12.7(P:GND) E13.7(P:GND) E14.7(P:GND) E15.8(GND) E16.7(P:GND) E17.7(P:GND) E18.7(P:GND) E19.7(P:GND) E20.1(P:GND) E21.7(P:GND) E22.8(GND) E23.7(P:GND) E24.7(P:GND) E25.1(GND) E26.7(P:GND) E27.7(P:GND) E28.7(P:GND) E29.7(P:GND) E30.1(GND) E31.7(P:GND) E32.7(GND) E33.7(GND) E34.7(GND) E35.7(P:GND) E36.1(P:GND) E37.7(GND) E38.7(P:GND) E39.1(P:GND) E40.1(P:GND) E41.1(GND) E42.7(P:GND) E43.7(P:GND) E44.7(P:GND) E45.1(P:GND) E46.1(P:GND) E47.8(GND) E48.7(P:GND) E49.8(GND) E50.8(GND) E51.1(GND) E52.7(P:GND) E53.8(GND) E54.7(P:GND)
VCC: E1.16(VCC) E2.16(VCC) E3.16(VCC) E4.14(P:VCC) E5.14(P:VCC) E6.16(VCC) E7.14(P:VCC) E8.8(VCC) E9.14(P:VCC) E10.16(VCC) E11.8(P:VCC) E12.14(P:VCC) E13.14(P:VCC) E14.14(P:VCC) E15.16(VCC) E16.14(P:VCC) E17.14(P:VCC) E18.14(P:VCC) E19.14(P:VCC) E20.8(P:VCC) E21.14(P:VCC) E22.16(VCC) E23.14(P:VCC) E24.14(P:VCC) E25.8(VCC) E26.14(P:VCC) E27.14(P:VCC) E28.14(P:VCC) E29.14(P:VCC) E30.8(VCC) E31.14(P:VCC) E32.14(VCC) E33.14(VCC) E34.14(VCC) E35.14(P:VCC) E36.8(P:VCC) E37.14(VCC) E38.14(P:VCC) E39.8(P:VCC) E40.8(P:VCC) E41.8(VCC) E42.14(P:VCC) E43.14(P:VCC) E44.14(P:VCC) E45.8(P:VCC) E46.8(P:VCC) E47.16(VCC) E48.14(P:VCC) E49.16(VCC) E50.16(VCC) E51.8(VCC) E52.14(P:VCC) E53.16(VCC) E54.14(P:VCC)

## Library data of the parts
C1-C54 C58 = rcl:C-US: CAPACITOR, American symbol
C55-C57 = rcl:CPOL-US: POLARIZED CAPACITOR, American symbol
E1 E6 E50 = dec-con:DEC8235: 4-bit data selector
E2 E3 E10 E47 E49 = dec-con:DEC8271: Parallel Load Shift Register
E4 E5 E9 E14 E18 E19 E24 E28 E44 E52 = 74xx-jameco:74*00: Quad 2-input NAND gate
E7 E16 E26 E31 E35 = dec-con:DS8881: Quad 2-input NAND gate, open collector
E8 E25 E30 E41 E51 = dec-con:SP384: Quad OR gate
E11 E20 E36 E39 E40 E45 E46 = dec-con:SP380: Quad NOR gate (use 8640)
E12 E21 E29 E42 E54 = 74xx-jameco:74*10: Triple 3-input NAND gate
E13 E17 = 74xx-jameco:74*74: Dual D type positive edge triggered FLIP FLOP, preset and clear
E15 E53 = dec-con:8266: Quad 2-1 selector
E22 = dec-con:DEC8251: BCD Decoder
E23 E27 E48 = 74xx-jameco:74*04: Hex INVERTER
E32-E34 E37 = dec-con:SP314: 7-Input NOR gate
E38 E43 = 74xx-jameco:74*20: Dual 4-input NAND gate
EDGE = dec-con:QUAD: Quad-Height DEC board
J1 = jumper:J: Bridge
R1-R8 = rcl:R-US_: RESISTOR, American symbol
U$1 = dec-con:OUTLINE-*: Board outlines for DEC boards.

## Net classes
1 Supply: width 0.762 mm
